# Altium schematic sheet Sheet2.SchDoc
size A3
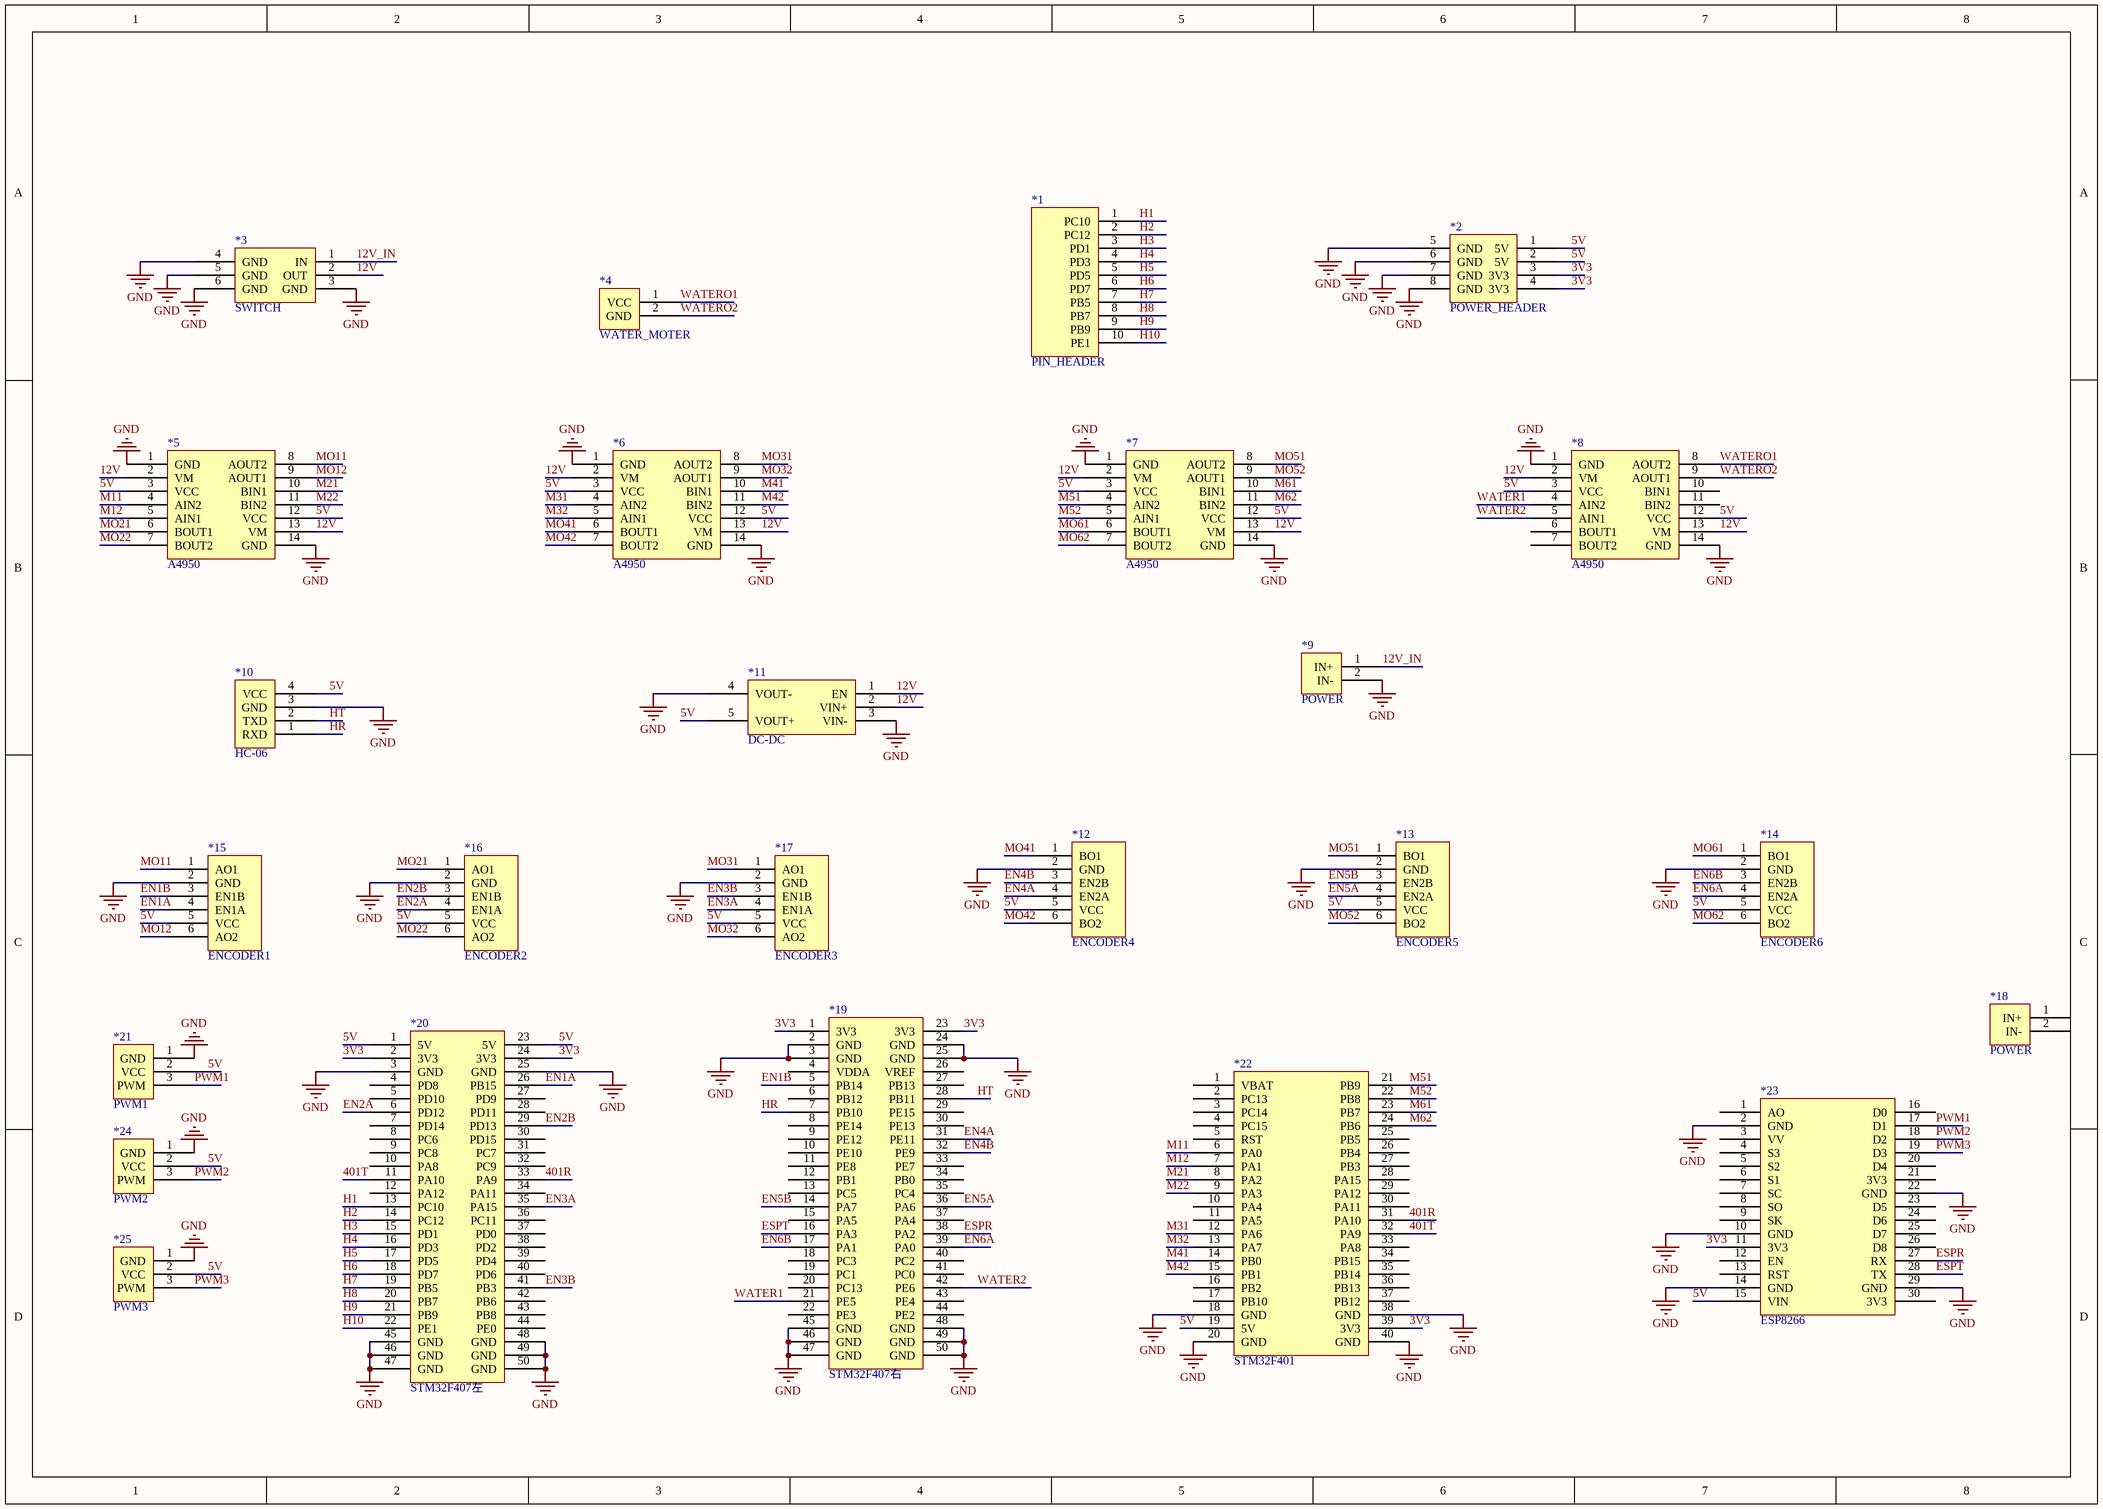
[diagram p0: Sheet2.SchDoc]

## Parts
*1  PIN_HEADER  [PIN_HEADER]
*2  POWER_HEADER  [POWER_HEADER]
*3  SWITCH  [SIWITCH]
*4  WATER_MOTER  [WATER_HEADER]
*5  A4950  [A4950]
*6  A4950  [A4950]
*7  A4950  [A4950]
*8  A4950  [A4950]
*9  POWER  [POWER]
*10  HC-06  [HC-06]
*11  DC-DC  [DC-DC]
*12  ENCODER4  [ENCODER2]
*13  ENCODER5  [ENCODER2]
*14  ENCODER6  [ENCODER2]
*15  ENCODER1  [ENCODER1]
*16  ENCODER2  [ENCODER1]
*17  ENCODER3  [ENCODER1]
*18  POWER  [POWER]
*19  STM32F407右  [STM32F407左]
*20  STM32F407左  [STM32F407左]
*21  PWM1  [PWM]
*22  STM32F401  [STM32F401CCU6]
*23  ESP8266  [ESP]
*24  PWM2  [PWM]
*25  PWM3  [PWM]

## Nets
GND: *2.5(GND) *2.6(GND) *2.7(GND) *2.8(GND) *3.3(GND) *3.4(GND) *3.5(GND) *3.6(GND) *5.1(GND) *5.14(GND) *6.1(GND) *6.14(GND) *7.1(GND) *7.14(GND) *8.1(GND) *8.14(GND) *9.2(IN-) *10.3(GND) *11.3(VIN-) *11.4(VOUT-) *12.2(GND) *13.2(GND) *14.2(GND) *15.2(GND) *16.2(GND) *17.2(GND) *19.2(GND) *19.3(GND) *19.24(GND) *19.25(GND) *19.45(GND) *19.46(GND) *19.47(GND) *19.48(GND) *19.49(GND) *19.50(GND) *20.3(GND) *20.25(GND) *20.45(GND) *20.46(GND) *20.47(GND) *20.48(GND) *20.49(GND) *20.50(GND) *21.1(GND) *22.18(GND) *22.20(GND) *22.38(GND) *22.40(GND) *23.2(GND) *23.10(GND) *23.14(GND) *23.22(GND) *23.29(GND) *24.1(GND) *25.1(GND)
3V3: *2.3(3V3) *2.4(3V3) *19.1(3V3) *19.23(3V3) *20.2(3V3) *20.24(3V3) *22.39(3V3) *23.11(3V3)
5V: *2.1(5V) *2.2(5V) *5.3(VCC) *5.12(VCC) *6.3(VCC) *6.12(VCC) *7.3(VCC) *7.12(VCC) *8.3(VCC) *8.12(VCC) *10.4(VCC) *11.5(VOUT+) *12.5(VCC) *13.5(VCC) *14.5(VCC) *15.5(VCC) *16.5(VCC) *17.5(VCC) *20.1(5V) *20.23(5V) *21.2(VCC) *22.19(5V) *23.15(VIN) *24.2(VCC) *25.2(VCC)
12V: *3.2(OUT) *5.2(VM) *5.13(VM) *6.2(VM) *6.13(VM) *7.2(VM) *7.13(VM) *8.2(VM) *8.13(VM) *11.1(EN) *11.2(VIN+)
12V_IN: *3.1(IN) *9.1(IN+)
401R: *20.33(PA9) *22.31(PA10)
401T: *20.11(PA10) *22.32(PA9)
EN1A: *15.4(EN1A) *20.26(PB15)
EN1B: *15.3(EN1B) *19.5(PB14)
EN2A: *16.4(EN1A) *20.6(PD12)
EN2B: *16.3(EN1B) *20.29(PD13)
EN3A: *17.4(EN1A) *20.35(PA15)
EN3B: *17.3(EN1B) *20.41(PB3)
EN4A: *12.4(EN2A) *19.31(PE11)
EN4B: *12.3(EN2B) *19.32(PE9)
EN5A: *13.4(EN2A) *19.36(PA6)
EN5B: *13.3(EN2B) *19.14(PA7)
EN6A: *14.4(EN2A) *19.39(PA0)
EN6B: *14.3(EN2B) *19.17(PA1)
ESPR: *19.38(PA2) *23.27(RX)
ESPT: *19.16(PA3) *23.28(TX)
H1: *1.1(PC10) *20.13(PC10)
H2: *1.2(PC12) *20.14(PC12)
H3: *1.3(PD1) *20.15(PD1)
H4: *1.4(PD3) *20.16(PD3)
H5: *1.5(PD5) *20.17(PD5)
H6: *1.6(PD7) *20.18(PD7)
H7: *1.7(PB5) *20.19(PB5)
H8: *1.8(PB7) *20.20(PB7)
H9: *1.9(PB9) *20.21(PB9)
H10: *1.10(PE1) *20.22(PE1)
HR: *10.1(RXD) *19.7(PB10)
HT: *10.2(TXD) *19.28(PB11)
M11: *5.4(AIN2) *22.6(PA0)
M12: *5.5(AIN1) *22.7(PA1)
M21: *5.10(BIN1) *22.8(PA2)
M22: *5.11(BIN2) *22.9(PA3)
M31: *6.4(AIN2) *22.12(PA6)
M32: *6.5(AIN1) *22.13(PA7)
M41: *6.10(BIN1) *22.14(PB0)
M42: *6.11(BIN2) *22.15(PB1)
M51: *7.4(AIN2) *22.21(PB9)
M52: *7.5(AIN1) *22.22(PB8)
M61: *7.10(BIN1) *22.23(PB7)
M62: *7.11(BIN2) *22.24(PB6)
MO11: *5.8(AOUT2) *15.1(AO1)
MO12: *5.9(AOUT1) *15.6(AO2)
MO21: *5.6(BOUT1) *16.1(AO1)
MO22: *5.7(BOUT2) *16.6(AO2)
MO31: *6.8(AOUT2) *17.1(AO1)
MO32: *6.9(AOUT1) *17.6(AO2)
MO41: *6.6(BOUT1) *12.1(BO1)
MO42: *6.7(BOUT2) *12.6(BO2)
MO51: *7.8(AOUT2) *13.1(BO1)
MO52: *7.9(AOUT1) *13.6(BO2)
MO61: *7.6(BOUT1) *14.1(BO1)
MO62: *7.7(BOUT2) *14.6(BO2)
PWM1: *21.3(PWM) *23.17(D1)
PWM2: *23.18(D2) *24.3(PWM)
PWM3: *23.19(D3) *25.3(PWM)
WATER1: *8.4(AIN2) *19.21(PE5)
WATER2: *8.5(AIN1) *19.42(PE6)
WATERO1: *4.1(VCC) *8.8(AOUT2)
WATERO2: *4.2(GND) *8.9(AOUT1)

Not connected (* = marked no-connect by the designer): *8 6(BOUT1) 7(BOUT2) 10(BIN1) 11(BIN2); *18 1(IN+) 2(IN-); *19 4(VDDA) 6(PB12) 8(PE14) 9(PE12) 10(PE10) 11(PE8) 12(PB1) 13(PC5) 15(PA5) 18(PC3) 19(PC1) 20(PC13) 22(PE3) 26(VREF) 27(PB13) 29(PE15) 30(PE13) 33(PE7) 34(PB0) 35(PC4) 37(PA4) 40(PC2) 41(PC0) 43(PE4) 44(PE2); *20 4(PD8) 5(PD10) 7(PD14) 8(PC6) 9(PC8) 10(PA8) 12(PA12) 27(PD9) 28(PD11) 30(PD15) 31(PC7) 32(PC9) 34(PA11) 36(PC11) 37(PD0) 38(PD2) 39(PD4) 40(PD6) 42(PB6) 43(PB8) 44(PE0); *22 1(VBAT) 2(PC13) 3(PC14) 4(PC15) 5(RST) 10(PA4) 11(PA5) 16(PB2) 17(PB10) 25(PB5) 26(PB4) 27(PB3) 28(PA15) 29(PA12) 30(PA11) 33(PA8) 34(PB15) 35(PB14) 36(PB13) 37(PB12); *23 1(AO) 3(VV) 4(S3) 5(S2) 6(S1) 7(SC) 8(SO) 9(SK) 12(EN) 13(RST) 16(D0) 20(D4) 21(3V3) 23(D5) 24(D6) 25(D7) 26(D8) 30(3V3)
